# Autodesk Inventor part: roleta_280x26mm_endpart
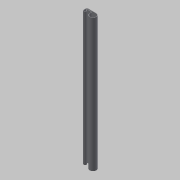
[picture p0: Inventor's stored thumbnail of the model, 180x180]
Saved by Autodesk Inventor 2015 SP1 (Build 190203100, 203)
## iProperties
Created: 2015-06
Part Number: roleta_280x26mm_endpart
Material: Generic
Document SubType Name: Modeling
Designer: uidn2323
Density: 1 g/cm^3
Appearance: Default
Author: uidn2323
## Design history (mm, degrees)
sketch "Sketch9"
  geometry: L1 (13.17, -2.949)-(13.17, -2.165); L2 (11.706, -0.701)-(7.314, -0.701); L3 (2.499, -4.802)-(19.933, -4.802); L4 (0.24, -4.8)-(0.24, -0.701); L5 (7.314, -0.701)-(5.516, -0.701); L6 (5.516, -0.701)-(3.476, -0.701); L7 (3.476, -0.701)-(3.476, -1.809); L8 (3.24, -4.8)-(3.24, -4.453); L9 (2.134, -4.8)-(19.568, -4.8); L10 (8.827, -1.117)-(12.721, -1.117); L11 (19.866, 2.227)-(3.168, 2.227); L12 (1.04, -0.701)-(1.04, -4.8); L13 (2.676, -2.674)-(2.676, 0.099); L14 (2.676, 0.099)-(5.516, 0.099); L15 (5.516, 0.099)-(7.314, 0.099); L16 (7.314, 0.099)-(11.706, 0.099); L17 (13.97, -2.165)-(13.97, -3.06); L18 (19.866, 1.427)-(3.168, 1.427); A1 r 1.464 centre (11.706, -2.165) between (13.17, -2.165) and (11.706, -0.701); A2 r 2.928 centre (3.168, -0.701) between (3.168, 2.227) and (0.24, -0.701); A3 r 6.816 centre (19.933, -4.805) between (13.117, -4.8) and (13.117, -4.802); A4 r 3 centre (3.24, -4.8) between (0.24, -4.8) and (3.476, -1.809); A5 r 6.818 centre (19.933, -4.8) between (13.115, -4.8) and (13.115, -4.802); A6 r 2 centre (19.866, 0.227) between (20.142, 2.208) and (19.866, 2.227); A7 r 7.011 centre (19.933, -4.8) between (13.17, -2.949) and (20.142, 2.208); A8 r 2.128 centre (3.168, -0.701) between (3.168, 1.427) and (1.04, -0.701); A9 r 2.2 centre (3.24, -4.8) between (1.04, -4.8) and (2.676, -2.674); A10 r 2.264 centre (11.706, -2.165) between (13.97, -2.165) and (11.706, 0.099); A11 r 6.211 centre (19.933, -4.8) between (13.97, -3.06) and (20.071, 1.41); A12 r 1.2 centre (19.866, 0.227) between (20.071, 1.41) and (19.866, 1.427); 1 further point
  constraints: 37 end point, 24 point on circle, 12 centre point, 7 horizontal, 4 point on line, 3 tangent, 2 coincident, 2 perpendicular, 2 vertical, 11 other
  dimensions: "d183" = 2.928 radius of A2; "d184" = 1.464 radius of A1; "d185" = 4.392 distance of L2.start L2.end; "d187" = 3 radius of A4; "d211" = 2 radius of A6; "d227" = 0.8 distance between parallel lines of L11 L18
extrude "Extrusion3" join sketch "Sketch9" distance "d189" = 280.4; taper "d190" = 0 deg
sketch "Sketch10"
  geometry: L1 (13.17, -3.952)-(13.17, -2.165); L2 (11.706, -0.701)-(7.314, -0.701); L3 (2.499, -4.802)-(19.933, -4.802); L4 (15.979, -0.698)-(15.979, -4.198); L5 (0.24, -4.8)-(0.24, -0.701); L6 (13.17, 2.227)-(3.168, 2.227); L7 (7.314, -0.701)-(5.516, -0.701); L8 (5.516, -0.701)-(3.476, -0.701); L9 (3.476, -0.701)-(3.476, -1.809); L10 (3.24, -4.8)-(3.24, -4.453); L11 (23.029, -2.299)-(23.039, -2.285); L12 (2.134, -4.8)-(19.568, -4.8); L13 (26.346, -4.113)-(23.029, -2.299); L14 (26.346, -4.113)-(26.346, -7.113); L15 (19.933, -4.8)-(19.933, -4.453); A1 r 2.928 centre (13.051, -0.698) between (15.979, -0.698) and (13.17, 2.227); A2 r 1.464 centre (11.706, -2.165) between (13.17, -2.165) and (11.706, -0.701); A3 r 2.928 centre (3.168, -0.701) between (3.168, 2.227) and (0.24, -0.701); A4 r 4 centre (19.933, -4.805) between (15.979, -4.198) and (23.039, -2.285); A5 r 6.816 centre (19.933, -4.805) between (13.17, -3.952) and (26.346, -7.113); A6 r 3 centre (3.24, -4.8) between (0.24, -4.8) and (3.476, -1.809); 1 further point
  constraints: 31 end point, 12 point on circle, 6 centre point, 6 horizontal, 4 tangent, 4 vertical, 2 coincident, 1 perpendicular
  dimensions: "d202" = 6.816 radius of A5; "d203" = 4 radius of A4; "d204" = 2.928 radius of A1; "d205" = 10.00212 distance of L6.start L6.end; "d206" = 2.928 radius of A3; "d207" = 1.464 radius of A2; "d208" = 4.392 distance of L2.start L2.end; "d209" = 2.92801 distance between parallel lines of L6 L2; "d210" = 3 radius of A6
extrude "Extrusion5" cut sketch "Sketch9" stored distance "d228" = 10; taper "d229" = 0 deg
body "Solid1"
other parameters: "d122" = 6.83405, "d123" = 4.99923
